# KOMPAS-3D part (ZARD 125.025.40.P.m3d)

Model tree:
1. Булева операция:1
2. Булева операция:2
3. Булева операция:3
4. Булева операция:4
5. Булева операция:5
6. Булева операция:6
7. Булева операция:7
8. Булева операция:8
9. Булева операция:9
10. Булева операция:10
11. Булева операция:11
12. Булева операция:12
13. Булева операция:13
14. Булева операция:14
15. Булева операция:15
16. Булева операция:16
